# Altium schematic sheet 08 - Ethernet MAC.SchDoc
size B; CompanyName: Microchip Technology Inc.; Organization: Microchip Technology; Address1: 2355 West Chandler Blvd.; Address2: Chandler, AZ  85224; Address4: USA; DocumentNumber: 8; SheetNumber: 8; SheetTotal: 13; SheetTitle: Ethernet MAC
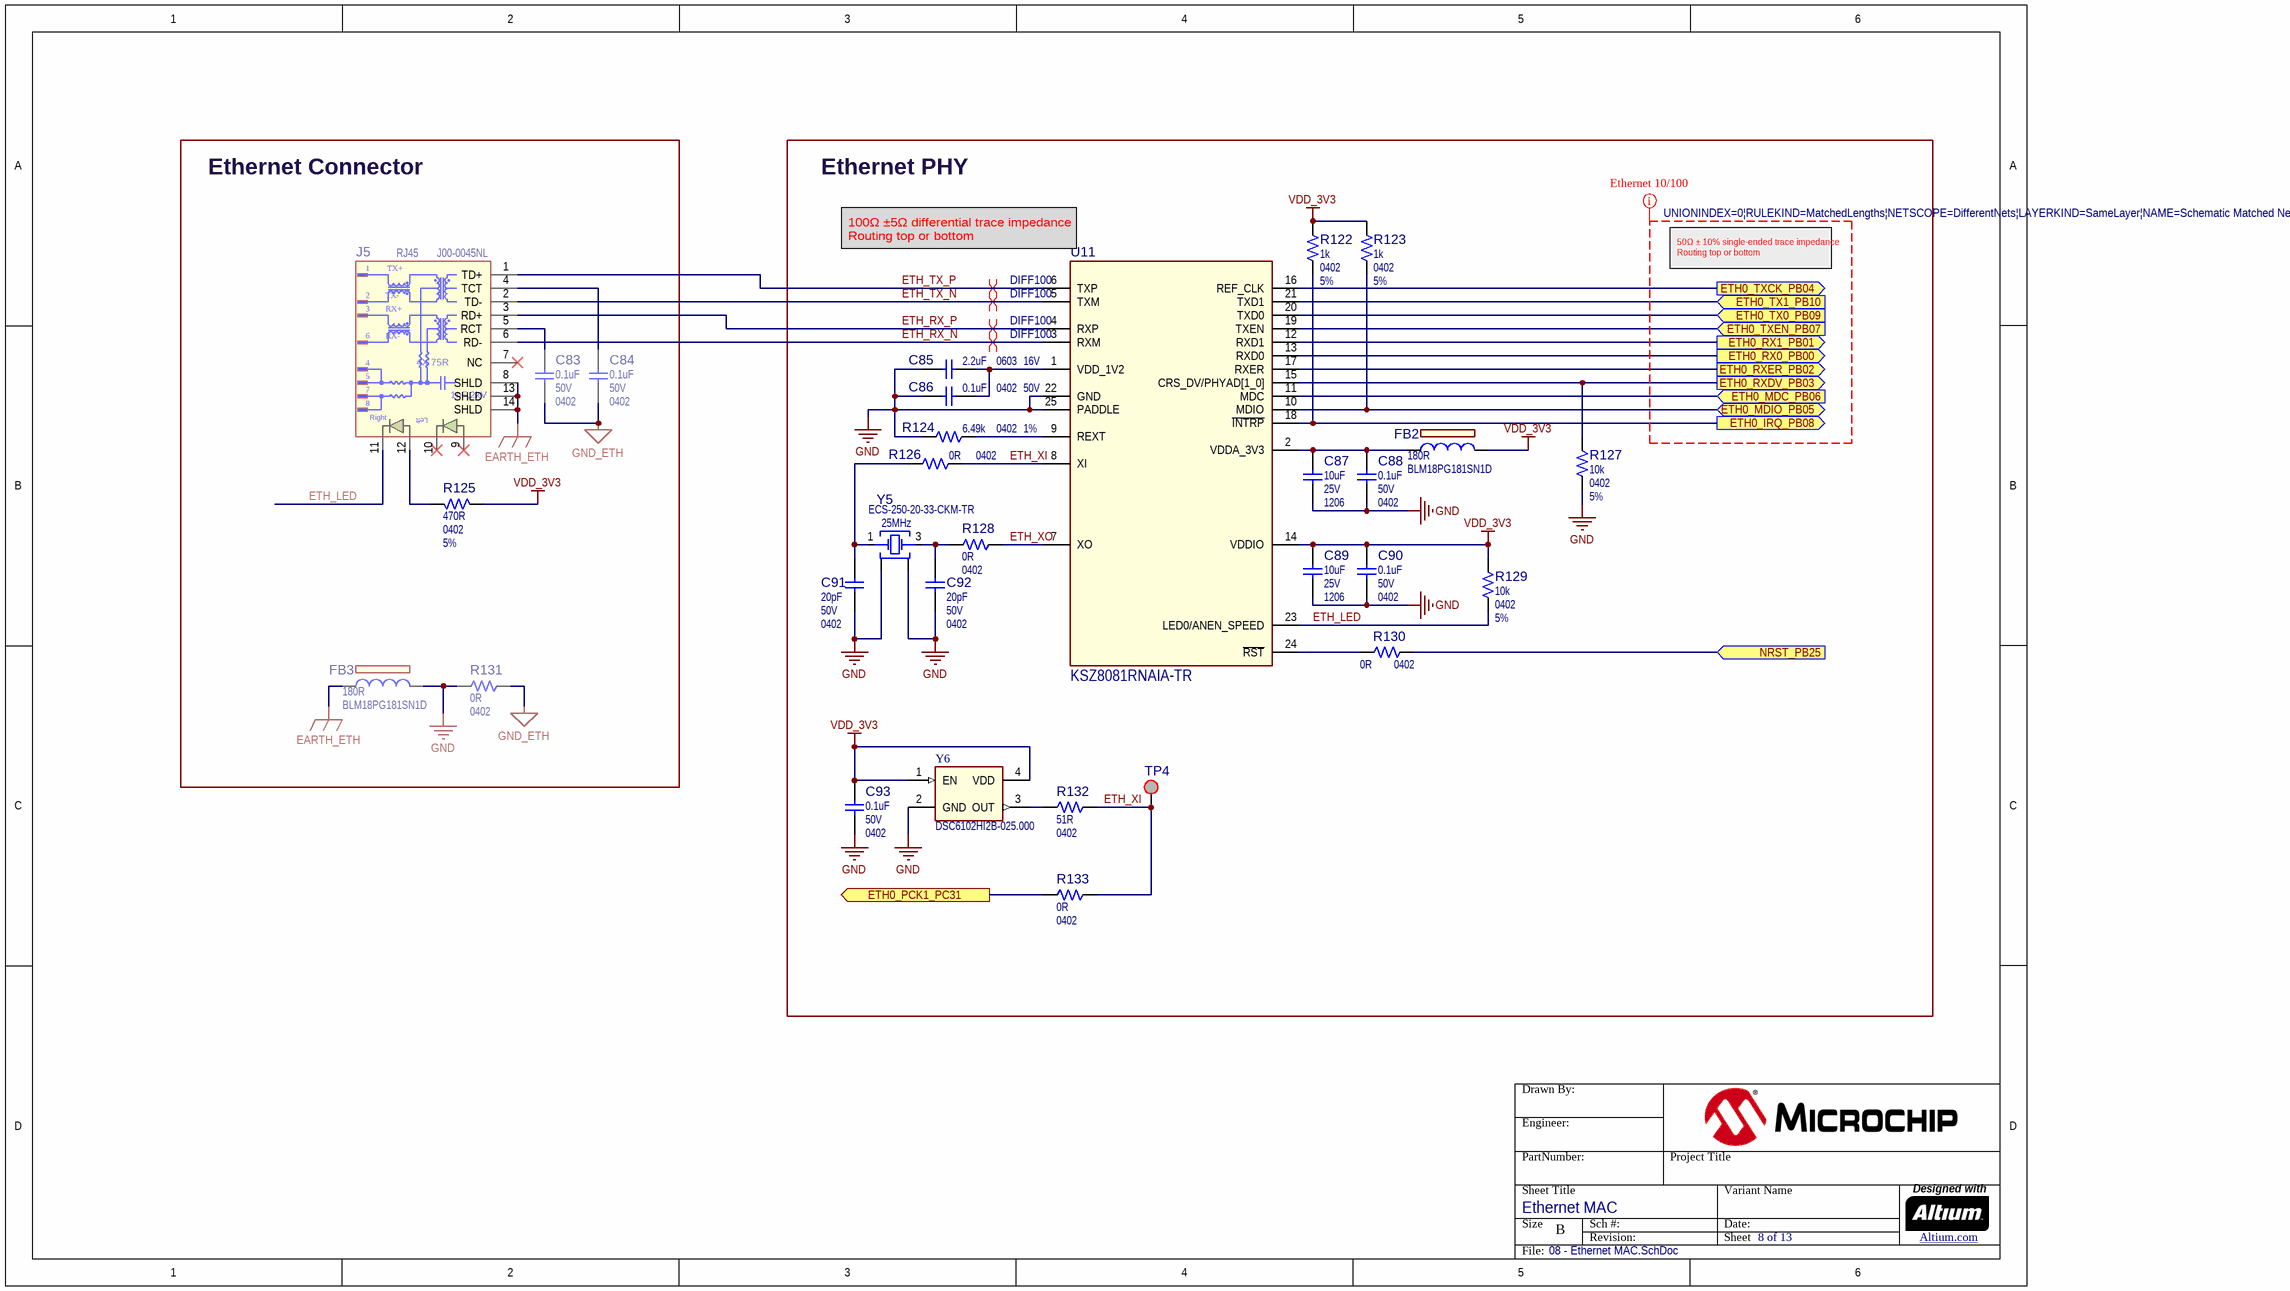
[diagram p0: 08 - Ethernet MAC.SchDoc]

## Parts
?  (no value)  (graphical)
C83  value 0.1uF  Voltage: 50V  Package: 0402  [CAP_C_0402]  (hidden comment: Capacitor NP)
C84  value 0.1uF  Voltage: 50V  Package: 0402  [CAP_C_0402]  (hidden comment: Capacitor NP)
C85  value 2.2uF  Voltage: 16V  Package: 0603  [CAP_C_0603]  (hidden comment: Capacitor NP)
C86  value 0.1uF  Voltage: 50V  Package: 0402  [CAP_C_0402]  (hidden comment: Capacitor NP)
C87  value 10uF  Voltage: 25V  Package: 1206  [CAP_C_1206]  (hidden comment: Capacitor NP)
C88  value 0.1uF  Voltage: 50V  Package: 0402  [CAP_C_0402]  (hidden comment: Capacitor NP)
C89  value 10uF  Voltage: 25V  Package: 1206  [CAP_C_1206]  (hidden comment: Capacitor NP)
C90  value 0.1uF  Voltage: 50V  Package: 0402  [CAP_C_0402]  (hidden comment: Capacitor NP)
C91  value 20pF  Voltage: 50V  Package: 0402  [CAP_C_0402]  (hidden comment: Capacitor NP)
C92  value 20pF  Voltage: 50V  Package: 0402  [CAP_C_0402]  (hidden comment: Capacitor NP)
C93  value 0.1uF  Voltage: 50V  Package: 0402  [CAP_C_0402]  (hidden comment: Capacitor NP)
FB2  value 180R  Manufacturer Part Number 1: BLM18PG181SN1D  [IND_C_0603]  (hidden comment: Ferrite Bead)
FB3  value 180R  Manufacturer Part Number 1: BLM18PG181SN1D  [IND_C_0603]  (hidden comment: Ferrite Bead)
J5  value RJ45  Manufacturer Part Number 1: J00-0045NL  [J00-0045NL_RJ45_connector]  (hidden comment: RJ45 J00-0045NL)
R122  value 1k  Package: 0402  Tolerance: 5%  [RES_C_0402]  (hidden comment: Resistor)
R123  value 1k  Package: 0402  Tolerance: 5%  [RES_C_0402]  (hidden comment: Resistor)
R124  value 6.49k  Package: 0402  Tolerance: 1%  [RES_C_0402]  (hidden comment: Resistor)
R125  value 470R  Package: 0402  Tolerance: 5%  [RES_C_0402]  (hidden comment: Resistor)
R126  value 0R  Package: 0402  [RES_C_0402]  (hidden comment: Resistor)
R127  value 10k  Package: 0402  Tolerance: 5%  [RES_C_0402]  (hidden comment: Resistor)
R128  value 0R  Package: 0402  [RES_C_0402]  (hidden comment: Resistor)
R129  value 10k  Package: 0402  Tolerance: 5%  [RES_C_0402]  (hidden comment: Resistor)
R130  value 0R  Package: 0402  [RES_C_0402]  (hidden comment: Resistor)
R131  value 0R  Package: 0402  [RES_C_0402]  (hidden comment: Resistor)
R132  value 51R  Package: 0402  [RES_C_0402]  (hidden comment: Resistor)
R133  value 0R  Package: 0402  [RES_C_0402]  (hidden comment: Resistor)
TP4  SMD Test Point  [TP_1x1_SMD]  (value not drawn)  (no BOM)
U11  value KSZ8081RNAIA-TR  [QFN-24_4X4]  (hidden comment: ETHERNET QFN-24)
Y5  value 25MHz  Manufacturer Part Number 1: ECS-250-20-33-CKM-TR  [CRYSTAL_L3.2W2.5H0.8]  (hidden comment: Crystal 4 pins 1-3)
Y6  Manufacturer Part Number 1: DSC6102HI2B-025.000  [DFN-4_VFLGA_1.6 X 1.2]  (hidden comment: OSCILLATOR 4 Pins)

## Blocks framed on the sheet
Ethernet Connector: C83 C84 FB3 J5 R125 R131
Ethernet PHY: C85-C93 FB2 R122-R124 R126-R130 R132 R133 TP4 U11 Y5 Y6

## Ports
ETH0_IRQ_PB08 (out), ETH0_MDC_PB06 (in), ETH0_MDIO_PB05 (bidir), ETH0_PCK1_PC31 (out), ETH0_RX0_PB00 (out), ETH0_RX1_PB01 (out), ETH0_RXDV_PB03 (out), ETH0_RXER_PB02 (out), ETH0_TX0_PB09 (in), ETH0_TX1_PB10 (in), ETH0_TXCK_PB04 (out), ETH0_TXEN_PB07 (in), NRST_PB25 (in)

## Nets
EARTH_ETH: FB3.1 J5.8(SHLD) J5.13(SHLD) J5.14(SHLD)
GND: C85.2 C86.2 C87.2 C88.2 C89.2 C90.2 C91.2 C92.2 C93.2 FB3.2 R124.1 R127.2 R131.1 U11.22(GND) U11.25(PADDLE) Y5.2 Y5.4 Y6.2(GND)
GND_ETH: C83.2 C84.2 R131.2
VDD_3V3: C89.1 C90.1 C93.1 FB2.2 R122.1 R123.1 R125.1 R129.1 U11.14(VDDIO) Y6.1(EN) Y6.4(VDD)
ETH0_IRQ_PB08: R122.2 U11.18(~{INTRP}) ; port ETH0_IRQ_PB08
ETH0_MDC_PB06: U11.11(MDC) ; port ETH0_MDC_PB06
ETH0_MDIO_PB05: R123.2 U11.10(MDIO) ; port ETH0_MDIO_PB05
ETH0_PCK1_PC31: R133.2 ; port ETH0_PCK1_PC31
ETH0_RX0_PB00: U11.13(RXD0) ; port ETH0_RX0_PB00
ETH0_RX1_PB01: U11.12(RXD1) ; port ETH0_RX1_PB01
ETH0_RXDV_PB03: R127.1 U11.15(CRS_DV/PHYAD[1_0]) ; port ETH0_RXDV_PB03
ETH0_RXER_PB02: U11.17(RXER) ; port ETH0_RXER_PB02
ETH0_TX0_PB09: U11.20(TXD0) ; port ETH0_TX0_PB09
ETH0_TX1_PB10: U11.21(TXD1) ; port ETH0_TX1_PB10
ETH0_TXCK_PB04: U11.16(REF_CLK) ; port ETH0_TXCK_PB04
ETH0_TXEN_PB07: U11.19(TXEN) ; port ETH0_TXEN_PB07
ETH_LED: J5.11(Ag) R129.2 U11.23(LED0/ANEN_SPEED)
ETH_RX_N: J5.6(RD-) U11.3(RXM)
ETH_RX_P: J5.3(RD+) U11.4(RXP)
ETH_TX_N: J5.2(TD-) U11.5(TXM)
ETH_TX_P: J5.1(TD+) U11.6(TXP)
ETH_XI: R126.1 R132.2 R133.1 TP4.1 U11.8(XI)
ETH_XO: R128.1 U11.7(XO)
NRST_PB25: R130.2 ; port NRST_PB25
NetC83_1: C83.1 J5.5(RCT)
NetC84_1: C84.1 J5.4(TCT)
NetC85_1: C85.1 C86.1 U11.1(VDD_1V2)
NetC87_1: C87.1 C88.1 FB2.1 U11.2(VDDA_3V3)
NetC91_1: C91.1 R126.2 Y5.1
NetC92_1: C92.1 R128.2 Y5.3
NetJ5_12: J5.12(Cg) R125.2
NetR124_2: R124.2 U11.9(REXT)
NetR130_1: R130.1 U11.24(~{RST})
NetR132_1: R132.1 Y6.3(OUT)

Not connected (* = marked no-connect by the designer): J5 7(NC)* 9(Ay)* 10(Cy)*

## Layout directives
net class ETH-RMII; rule Matched Net Lengths [Tolerance = 0.5mm]: (no net found under the mark)
differential pair; differential pair class DIFF100; net class DIFF100; rule Matched Net Lengths [Tolerance = 10mil]: ETH_RX_N, ETH_RX_P, ETH_TX_N, ETH_TX_P

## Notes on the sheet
- (near U11) 100Ω ±5Ω differential trace impedance
  Routing top or bottom
- 50Ω ± 10% single-ended trace impedance
  Routing top or bottom

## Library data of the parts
? = Title Block B
C83 C84 C86 C88 C90 C93 = CAP1463: Capacitor; Manufacturer 1: TDK Corporation; Manufacturer Part Number 1: C1005X7R1H104K050BB; Description_: CAP CER 0.1uF 50V 10% X7R SMD 0402; Dev Tools Status: Production; Tolerance: 10%; Temperature Coeffcient: X7R; Type: Ceramic; Owner: Jamus Griego; Populated: YES
C85 = CAP0597: Capacitor; Manufacturer 1: TDK; Manufacturer Part Number 1: C1608X5R1C225K; Description_: CAP CER 2.2uF 16V 10% X5R SMD 0603; Dev Tools Status: Production; Tolerance: 10%; Temperature Coeffcient: X5R; Type: Ceramic; Populated: Yes
C87 C89 = CAP1418: Capacitor; Manufacturer 1: Samsung Electro-Mechanics America, Inc; Manufacturer Part Number 1: CL31B106KAHNFNE; Description_: CAP CER 10uF 25V 10% X7R SMD 1206; Dev Tools Status: Design; Tolerance: 10%; Temperature Coeffcient: X7R; Type: Ceramic; Populated: YES; Owner: Sorin Stanoaia
C91 C92 = CAP0364: Capacitor; Manufacturer 1: Murata; Manufacturer Part Number 1: GRM1555C1H200JZ01D; Description_: CAP CER 20pF 50V 5% C0G SMD 0402; Dev Tools Status: Production; Tolerance: 5%; Temperature Coeffcient: C0G; Type: Ceramic; Populated: DNP
FB2 FB3 = IND1453: Manufacturer 1: Murata Electronics North America; Description_: FERRITE 180R 1.5A SMD 0603; Dev Tools Status: Design; Owner: Dragos Danaila; DCR: 0.09R; Saturation Current: 1.5A; Test Frequency: 100MHz; Populated: YES
J5 = CON1769: Manufacturer 1: Pulse Electronics Network; Description_: CON MODULAR RJ45 ETHERNET J00-0045NL; Dev Tools Status: Design; Owner: Ilie Galan; Populated: YES
R122 R123 = RSMT0316: Manufacturer 1: Panasonic; Manufacturer Part Number 1: ERJ-2GEJ102X; Description_: RES TKF 1k 5% 1/16W SMD 0402; Dev Tools Status: Production; Voltage: 50V; Temperature Coeffcient: 200ppm/C; Power: 1/16W; Owner: Tad Ahlvers; Populated: YES
R124 = RES1731: Manufacturer 1: Yageo; Manufacturer Part Number 1: RC0402FR-076K49L; Description_: RES TKF 6.49k 1% 1/16W SMD 0402; Dev Tools Status: Production; Voltage: 50V; Temperature Coeffcient: 100ppm/C; Power: 1/16W; Owner: Jesus Aviles; Populated: YES
R125 = RSMT1037: Manufacturer 1: Yageo; Manufacturer Part Number 1: RC0402JR-07470RL; Description_: RES TKF 470R 5% 1/16W SMD 0402; Dev Tools Status: Production; Voltage: 50V; Temperature Coeffcient: 100ppm/C; Power: 1/16W; Owner: Sompoch Loboonlert; Populated: Yes
R126 R128 R133 = RSMT1040: Manufacturer 1: Yageo; Manufacturer Part Number 1: RC0402JR-070RL; Description_: RES TKF 0R 1/16W SMD 0402; Dev Tools Status: Production; Power: 1/16W; Owner: Sompoch Loboonlert; Populated: DNP
R127 R129 = RSMT0439: Manufacturer 1: Vishay; Manufacturer Part Number 1: CRCW040210K0JNED; Description_: RES TKF 10k 5% 1/16W SMD 0402; Dev Tools Status: Production; Voltage: 50V; Temperature Coeffcient: 100ppm/C; Power: 1/16W; Populated: Yes
R130 R131 = RSMT1040: Manufacturer 1: Yageo; Manufacturer Part Number 1: RC0402JR-070RL; Description_: RES TKF 0R 1/16W SMD 0402; Dev Tools Status: Production; Power: 1/16W; Owner: Sompoch Loboonlert; Populated: Yes
R132 = RSMT1243: Manufacturer 1: Yageo; Manufacturer Part Number 1: RC0402FR-0751RL; Tolerance: 1%; Description_: RES TKF 51R 1% 1/16W SMD 0402; Dev Tools Status: Design; Voltage: 100V; Temperature Coeffcient: 100ppm/C; Current: 1A; Power: 1/16W; Owner: Ciprian Abramov; Populated: YES
TP4 = TEST-POINT: Test Point pad 1.00mm
U11 = MIC7404: Manufacturer 1: Microchip Technology; Description_: MCHP INTERFACE ETHERNET KSZ8081RNAIA-TR QFN-24; Dev Tools Status: Design; Owner: Ciprian Abramov; Populated: YES
Y5 = OSC1159: Crystal; Manufacturer 1: ECS Inc.; Description_: CRYSTAL 25MHz 20pF SMD L3.2W2.5H0.8; Dev Tools Status: Design; Owner: Ciprian Abramov; Tolerance: 10ppm; Load Capacitance: 20pF; Populated: DNP
Y6 = MIC8785: Manufacturer 1: Microchip Technology Inc; Description_: OSCILLATOR MEMS 25MHz DSC6102HI2B-025.000 SMD VFLGA-4; Dev Tools Status: Design; Value: DSC6102HI2B-025.000; Owner: Dragos Danaila; Populated: YES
